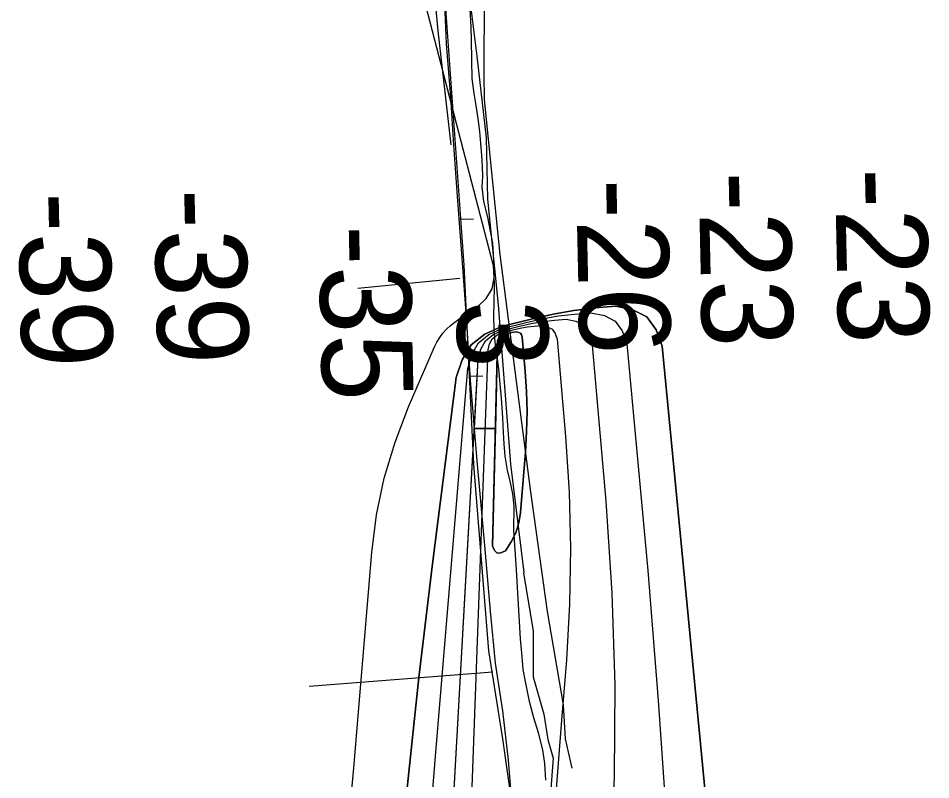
# Model space of a CAD drawing. Extents: x 3925854 to 3964121, y 224593 to 250589.
# Drawn here: x 3945050 to 3945720, y 240571 to 241130 of the extents above; entities that cross this region are included whole.
import ezdxf

# ---------------------------------------------------------------- set-up
doc = ezdxf.new("R2010")
doc.units = 0
for name, color, linetype in [('V-LEVE-TOET', 7, 'Continuous'), ('V-RIVR-EDGE', 7, 'Continuous'), ('V-RIVR-RANG', 7, 'Continuous'), ('V-TOPO-DPTH', 7, 'Continuous'), ('V-TOPO-MINR', 7, 'Continuous'), ('V-TOPO-WATR', 7, 'Continuous'), ('V-WETL-SWMP', 7, 'Continuous')]:
    doc.layers.add(name, color=color, linetype=linetype)

msp = doc.modelspace()

# ---------------------------------------------------------------- linework, layer by layer
at = {"layer": 'V-LEVE-TOET'}
for p, q in [((3945373.991, 240939.248), (3945299.13, 240931.667)), ((3945398.347, 240649.741), (3945263.417, 240639.286))]:
    msp.add_line(p, q, dxfattribs=at)
for points in [[(3945367.713, 241037.354), (3945358.094, 241121.053), (3945351.657, 241189.369)], [(3945391.962, 241147.757), (3945391.806, 241088.783), (3945391.923, 241070.693), (3945398.13, 241009.831), (3945403.359, 240956.88), (3945415.747, 240861.752), (3945425.733, 240784.129), (3945438.181, 240694.471), (3945450.084, 240625.798), (3945451.346, 240600.855), (3945456.287, 240579.22)]]:
    msp.add_lwpolyline(points, dxfattribs=at)
at = {"layer": 'V-RIVR-EDGE'}
for points in [[(3945358.155, 241213.322), (3945377.046, 240948.836), (3945384.131, 240802.424), (3945395.151, 240665.458), (3945405.384, 240600.91), (3945412.469, 240550.532), (3945424.276, 240415.927), (3945420.34, 240395.461), (3945406.171, 240393.887), (3945397.513, 240376.569), (3945399.087, 240327.765), (3945394.364, 240298.64), (3945392.79, 240289.194), (3945399.087, 240272.664), (3945395.938, 240235.667), (3945375.472, 240098.701), (3945352.644, 240015.262), (3945340.837, 239971.181), (3945325.094, 239873.573), (3945284.948, 239657.891), (3945260.546, 239558.708), (3945201.509, 239254.864), (3945178.682, 239129.705), (3945119.644, 238862.07)], [(3945374.801, 241196.891), (3945386.596, 241102.533), (3945393.476, 241042.576), (3945394.459, 240997.363), (3945402.322, 240919.714), (3945411.168, 240802.75), (3945420.997, 240723.135), (3945420.973, 240722.739)], [(3945420.953, 240722.818), (3945427.877, 240679.888), (3945427.877, 240646.469), (3945435.74, 240618.948), (3945438.689, 240600.273), (3945442.621, 240586.513), (3945440.655, 240560.957)]]:
    msp.add_lwpolyline(points, dxfattribs=at)
at = {"layer": 'V-TOPO-DPTH'}
for points in [[(3945288.965, 240502.042), (3945296.178, 240579.489), (3945309.278, 240737.821), (3945312.937, 240765.368), (3945318.36, 240792.47), (3945326.426, 240818.906), (3945336.256, 240844.898), (3945355.425, 240888.873), (3945357.215, 240892.404), (3945359.255, 240895.762), (3945361.669, 240898.862), (3945364.333, 240901.79), (3945367.267, 240904.488), (3945370.303, 240907.057), (3945373.492, 240909.434), (3945376.784, 240911.682), (3945387.015, 240918.218), (3945393.439, 240924.446), (3945397.892, 240931.447), (3945399.388, 240939.608), (3945398.913, 240948.543), (3945314.022, 241274.806)], [(3945288.965, 240502.042), (3945296.178, 240579.489), (3945309.278, 240737.821), (3945312.937, 240765.368), (3945318.36, 240792.47), (3945326.426, 240818.906), (3945336.256, 240844.898), (3945355.425, 240888.873), (3945357.215, 240892.404), (3945359.255, 240895.762), (3945361.669, 240898.862), (3945364.333, 240901.79), (3945367.267, 240904.488), (3945370.303, 240907.057), (3945373.492, 240909.434), (3945376.784, 240911.682), (3945387.015, 240918.218), (3945393.439, 240924.446), (3945397.892, 240931.447), (3945399.388, 240939.608), (3945398.913, 240948.543), (3945314.022, 241274.806)], [(3945622.668, 239892.343), (3945595.043, 240034.436), (3945587.449, 240079.187), (3945581.292, 240124.1), (3945577.29, 240169.257), (3945574.724, 240214.575), (3945572.838, 240272.374), (3945569.701, 240346.668), (3945565.614, 240420.901), (3945560.105, 240495.042), (3945553.647, 240569.121), (3945522.628, 240889.417), (3945518.242, 240901.514), (3945511.507, 240910.884), (3945501.246, 240916.163), (3945488.634, 240918.716), (3945473.2, 240917.471), (3945457.854, 240915.636), (3945442.64, 240912.916), (3945427.514, 240909.605), (3945404.734, 240903.924), (3945392.342, 240898.155), (3945382.269, 240890.325)], [(3945652.853, 240219.537), (3945574.724, 240214.575), (3945572.838, 240272.374), (3945569.701, 240346.668), (3945565.614, 240420.901), (3945560.105, 240495.042), (3945553.647, 240569.121), (3945522.628, 240889.417), (3945518.242, 240901.514), (3945511.507, 240910.884), (3945501.246, 240916.163), (3945488.634, 240918.716), (3945473.2, 240917.471), (3945457.854, 240915.636), (3945442.64, 240912.916), (3945427.514, 240909.605), (3945404.734, 240903.924), (3945392.342, 240898.155), (3945382.269, 240890.325)], [(3945392.897, 240893.289), (3945398.316, 240897.716), (3945405.127, 240900.991), (3945417.921, 240904.182), (3945426.408, 240906.04), (3945434.945, 240907.566), (3945443.556, 240908.596), (3945452.217, 240909.294), (3945459.27, 240907.853), (3945464.994, 240904.884), (3945468.724, 240899.624), (3945471.125, 240892.837), (3945481.364, 240775.417), (3945485.723, 240708.012), (3945488.067, 240640.583), (3945487.39, 240573.115), (3945484.699, 240505.623)], [(3945392.897, 240893.289), (3945398.316, 240897.716), (3945405.127, 240900.991), (3945417.921, 240904.182), (3945426.408, 240906.04), (3945434.945, 240907.566), (3945443.556, 240908.596), (3945452.217, 240909.294), (3945459.27, 240907.853), (3945464.994, 240904.884), (3945468.724, 240899.624), (3945471.125, 240892.837), (3945481.364, 240775.417), (3945485.723, 240708.012), (3945488.067, 240640.583), (3945487.39, 240573.115), (3945484.699, 240505.623)], [(3945399.952, 240820.735), (3945397.948, 240742.559), (3945399.455, 240739.281), (3945401.466, 240737.374), (3945404.235, 240737.521), (3945407.507, 240739.039), (3945411.803, 240745.476), (3945415.249, 240752.253), (3945417.422, 240759.539), (3945418.745, 240767.164), (3945422.344, 240811.854), (3945423.157, 240826.56), (3945423.478, 240841.264), (3945423.06, 240855.966), (3945422.149, 240870.667), (3945419.915, 240896.281), (3945419.392, 240897.761), (3945418.578, 240898.908), (3945417.33, 240899.555), (3945415.792, 240899.87), (3945412.027, 240899.493), (3945408.315, 240898.756), (3945404.049, 240897.341), (3945402.889, 240896.373)], [(3945079.171, 239086.627), (3945133.342, 239136.688), (3945162.718, 239262.687), (3945163.374, 239265.574), (3945164.007, 239268.465), (3945164.608, 239271.364), (3945165.186, 239274.267), (3945165.74, 239277.176), (3945166.283, 239280.086), (3945166.811, 239282.999), (3945167.328, 239285.914), (3945334.284, 240042.622), (3945338.985, 240080.256), (3945343.092, 240117.946), (3945346.309, 240155.724), (3945348.932, 240193.558), (3945349.586, 240204.94), (3945352.082, 240248.51), (3945354.567, 240292.08), (3945357.035, 240335.652), (3945359.492, 240379.223), (3945387.62, 240879.833), (3945389.563, 240887.136), (3945392.897, 240893.289)], [(3945400.159, 240828.84), (3945384.759, 240828.906), (3945387.62, 240879.833), (3945389.563, 240887.136), (3945392.897, 240893.289)], [(3945402.889, 240896.373), (3945401.815, 240893.438), (3945400.159, 240828.84)], [(3945382.269, 240890.325), (3945375.675, 240879.403), (3945371.401, 240866.419), (3945353.948, 240729.516), (3945344.014, 240645.92), (3945335.034, 240562.229), (3945327.483, 240478.398), (3945320.885, 240394.472), (3945303.717, 240149.355), (3945302.417, 240133.051), (3945300.908, 240116.768), (3945125.024, 239293.971)], [(3945382.269, 240890.325), (3945375.675, 240879.403), (3945371.401, 240866.419), (3945353.948, 240729.516), (3945344.014, 240645.92), (3945335.034, 240562.229), (3945327.483, 240478.398), (3945320.885, 240394.472), (3945303.717, 240149.355), (3945302.417, 240133.051), (3945300.908, 240116.768), (3945125.024, 239293.971)], [(3945133.342, 239136.688), (3945162.718, 239262.687), (3945163.374, 239265.574), (3945164.007, 239268.465), (3945164.608, 239271.364), (3945165.186, 239274.267), (3945165.74, 239277.176), (3945166.283, 239280.086), (3945166.811, 239282.999), (3945167.328, 239285.914), (3945334.284, 240042.622), (3945338.985, 240080.256), (3945343.092, 240117.946), (3945346.309, 240155.724), (3945348.932, 240193.558), (3945349.586, 240204.94), (3945352.082, 240248.51), (3945354.567, 240292.08), (3945357.035, 240335.652), (3945359.492, 240379.223), (3945384.383, 240822.213), (3945384.759, 240828.906), (3945400.159, 240828.84), (3945399.952, 240820.735)]]:
    msp.add_lwpolyline(points, dxfattribs=at)
at = {"layer": 'V-TOPO-MINR'}
for points in [[(3945288.965, 240502.042), (3945296.178, 240579.489), (3945309.278, 240737.821), (3945312.937, 240765.368), (3945318.36, 240792.47), (3945326.426, 240818.906), (3945336.256, 240844.898), (3945355.425, 240888.873), (3945357.215, 240892.404), (3945359.255, 240895.762), (3945361.669, 240898.862), (3945364.333, 240901.79), (3945367.267, 240904.488), (3945370.303, 240907.057), (3945373.492, 240909.434), (3945376.784, 240911.682), (3945387.015, 240918.218), (3945393.439, 240924.446), (3945397.892, 240931.447), (3945399.388, 240939.608), (3945398.913, 240948.543), (3945314.022, 241274.806)], [(3945382.269, 240890.325), (3945392.342, 240898.155), (3945404.734, 240903.924), (3945427.514, 240909.605), (3945442.64, 240912.916), (3945457.854, 240915.636), (3945473.2, 240917.471), (3945488.634, 240918.716), (3945501.246, 240916.163), (3945511.507, 240910.884), (3945518.242, 240901.514), (3945522.628, 240889.417), (3945553.647, 240569.121), (3945560.105, 240495.042), (3945565.614, 240420.901), (3945569.701, 240346.668), (3945572.838, 240272.374), (3945574.724, 240214.575), (3945577.29, 240169.257), (3945581.292, 240124.1), (3945587.449, 240079.187), (3945595.043, 240034.436), (3945622.668, 239892.343)], [(3945387.714, 240891.779), (3945395.379, 240897.921), (3945404.931, 240902.457), (3945422.708, 240906.891), (3945434.517, 240909.475), (3945446.394, 240911.599), (3945458.374, 240913.032), (3945470.422, 240914.004), (3945480.25, 240912.005), (3945488.234, 240907.879), (3945493.455, 240900.563), (3945496.833, 240891.12), (3945512.088, 240724.516), (3945519.869, 240629.092), (3945526.381, 240533.595), (3945530.992, 240437.986), (3945534.334, 240342.304), (3945536.601, 240251.512), (3945539.818, 240187.3), (3945545.167, 240123.32), (3945553.716, 240059.689), (3945564.398, 239996.29), (3945603.534, 239794.981)], [(3945392.897, 240893.289), (3945398.316, 240897.716), (3945405.127, 240900.991), (3945417.921, 240904.182), (3945426.408, 240906.04), (3945434.945, 240907.566), (3945443.556, 240908.596), (3945452.217, 240909.294), (3945459.27, 240907.853), (3945464.994, 240904.884), (3945468.724, 240899.624), (3945471.125, 240892.837), (3945481.364, 240775.417), (3945485.723, 240708.012), (3945488.067, 240640.583), (3945487.39, 240573.115), (3945484.699, 240505.623)], [(3945397.939, 240894.824), (3945401.201, 240897.524), (3945405.324, 240899.525), (3945413.114, 240901.468), (3945418.284, 240902.599), (3945423.483, 240903.529), (3945428.727, 240904.156), (3945434.002, 240904.581), (3945438.298, 240903.703), (3945441.784, 240901.895), (3945444.056, 240898.692), (3945445.518, 240894.558), (3945451.756, 240823.041), (3945454.306, 240781.994), (3945455.49, 240740.941), (3945454.626, 240699.881), (3945452.396, 240658.815), (3945448.88, 240614.527), (3945443.968, 240551.305)], [(3945133.342, 239136.688), (3945162.718, 239262.687), (3945163.374, 239265.574), (3945164.007, 239268.465), (3945164.608, 239271.364), (3945165.186, 239274.267), (3945165.74, 239277.176), (3945166.283, 239280.086), (3945166.811, 239282.999), (3945167.328, 239285.914), (3945334.284, 240042.622), (3945338.985, 240080.256), (3945343.092, 240117.946), (3945346.309, 240155.724), (3945348.932, 240193.558), (3945349.586, 240204.94), (3945352.082, 240248.51), (3945354.567, 240292.08), (3945357.035, 240335.652), (3945359.492, 240379.223), (3945387.62, 240879.833), (3945389.563, 240887.136), (3945392.897, 240893.289)], [(3945155.778, 239131.865), (3945184.493, 239264.7), (3945185.365, 239268.842), (3945186.189, 239272.994), (3945186.972, 239277.154), (3945187.719, 239281.32), (3945215.33, 239439.401), (3945218.985, 239457.037), (3945223.362, 239474.469), (3945228.823, 239491.591), (3945365.28, 240109.87), (3945365.809, 240114.117), (3945366.264, 240118.371), (3945366.608, 240122.635), (3945366.878, 240126.906), (3945367.084, 240131.183), (3945367.278, 240135.46), (3945367.455, 240139.738), (3945367.62, 240144.017), (3945394.863, 240886.629), (3945395.97, 240891.076), (3945397.939, 240894.824)], [(3945114.556, 239142.154), (3945144.386, 239261.072), (3945145.117, 239264.618), (3945145.647, 239268.185), (3945145.874, 239271.784), (3945145.893, 239275.571), (3945145.877, 239279.284), (3945146.016, 239282.985), (3945146.385, 239286.671), (3945146.909, 239290.346), (3945321.949, 240117.352), (3945324.353, 240144.333), (3945326.373, 240171.352), (3945333.024, 240275.244), (3945338.313, 240354.22), (3945343.91, 240433.174), (3945349.969, 240512.094), (3945356.336, 240590.991), (3945379.933, 240873.073), (3945382.88, 240883.229), (3945387.714, 240891.779)], [(3945125.024, 239293.971), (3945300.908, 240116.768), (3945302.417, 240133.051), (3945303.717, 240149.355), (3945320.885, 240394.472), (3945327.483, 240478.398), (3945335.034, 240562.229), (3945344.014, 240645.92), (3945353.948, 240729.516), (3945371.401, 240866.419), (3945375.675, 240879.403), (3945382.269, 240890.325)]]:
    msp.add_lwpolyline(points, dxfattribs=at)
at = {"layer": 'V-TOPO-WATR'}
msp.add_lwpolyline([(3945402.889, 240896.373), (3945404.049, 240897.341), (3945408.315, 240898.756), (3945412.027, 240899.493), (3945415.792, 240899.87), (3945417.33, 240899.555), (3945418.578, 240898.908), (3945419.392, 240897.761), (3945419.915, 240896.281), (3945422.149, 240870.667), (3945423.06, 240855.966), (3945423.478, 240841.264), (3945423.157, 240826.56), (3945422.344, 240811.854), (3945418.745, 240767.164), (3945417.422, 240759.539), (3945415.249, 240752.253), (3945411.803, 240745.476), (3945407.507, 240739.039), (3945404.235, 240737.521), (3945401.466, 240737.374), (3945399.455, 240739.281), (3945397.948, 240742.559), (3945401.815, 240893.438), (3945402.889, 240896.373)], dxfattribs=at)
at = {"layer": 'V-WETL-SWMP'}
for p, q in [((3945373.334, 240982.674), (3945384.163, 240982.871)), ((3945381.37, 240867.369), (3945390.853, 240867.541))]:
    msp.add_line(p, q, dxfattribs=at)
for points in [[(3945361.869, 241164.693), (3945364.041, 241111.515), (3945367.267, 241072.447), (3945369.524, 241037.222), (3945372.326, 240996.242), (3945375.955, 240947.386), (3945378.432, 240913.975), (3945381.55, 240864.519), (3945386.583, 240805.158), (3945392.091, 240742.969), (3945396.329, 240694.51), (3945399.968, 240656.446), (3945405.354, 240621.391), (3945409.617, 240585.035), (3945414.434, 240524.366)], [(3945428.483, 240616.307), (3945425.178, 240628.243), (3945422.204, 240643), (3945420.68, 240651.69), (3945419.873, 240661.381), (3945418.696, 240674.304), (3945415.691, 240724.969), (3945413.675, 240754.241), (3945413.957, 240771.687), (3945413.045, 240780.976), (3945411.122, 240790.074), (3945409.09, 240798.366), (3945407.38, 240808.571), (3945406.667, 240817.656), (3945406.048, 240826.034), (3945405.553, 240836.63), (3945404.695, 240851.164), (3945403.795, 240861.663), (3945402.7, 240872.769), (3945401.295, 240883.173), (3945400.078, 240892.263), (3945399.268, 240901.652), (3945398.967, 240911.54), (3945399.587, 240932.412), (3945399.089, 240952.489), (3945398.311, 240965.005), (3945396.69, 240973.998), (3945394.575, 240984.107), (3945391.772, 240995.836), (3945390.572, 241006.54), (3945390.849, 241013.8), (3945390.829, 241021.566), (3945390.308, 241029.742), (3945389.591, 241038.424), (3945388.674, 241047.208), (3945387.46, 241056.601), (3945386.147, 241066.197), (3945384.627, 241075.19), (3945383.227, 241086.097), (3945382.864, 241099.718), (3945382.714, 241114.446), (3945382.41, 241124.031), (3945381.736, 241136.848)], [(3945437.287, 240570.423), (3945436.607, 240582.635), (3945435.099, 240592.837), (3945431.798, 240605.278), (3945428.483, 240616.307)]]:
    msp.add_lwpolyline(points, dxfattribs=at)

# ---------------------------------------------------------------- texts
at = {"layer": 'V-RIVR-RANG'}
for s, p in [('-23', (3945549.427, 241017.419)), ('-23', (3945649.596, 241019.884)), ('-26', (3945459.424, 241012.037)), ('-39', (3945149.412, 241004.671)), ('-39', (3945049.542, 241002.213)), ('-35', (3945270.322, 240977.893)), ('3', (3945371.566, 240922.607))]:
    msp.add_text(s, height=67, rotation=271.263028, dxfattribs=at).set_placement(p)

doc.saveas('drawing.dxf')
